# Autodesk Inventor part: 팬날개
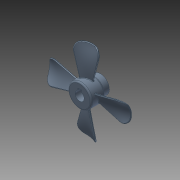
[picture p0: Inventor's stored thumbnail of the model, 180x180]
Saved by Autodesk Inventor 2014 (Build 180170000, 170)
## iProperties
Company: 한국ATC센터
Created: 2016-06
Part Number: 팬날개
Document SubType Name: Modeling
Designer: mdu
Density: 1.06 g/cm^3
Material: ABS 플라스틱
Mass: 29.2304 g
Surface Area: 148.222 cm^2
Volume: 27.5759 cm^3
Appearance: 강청색
Author: mdu
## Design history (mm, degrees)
sketch "스케치1"
  geometry: L1 (-15, 0)-(15, 0); L2 (-15, 0)-(-15, 17); L3 (-15, 17)-(5, 17); L4 (5, 17)-(5, 13); L5 (5, 13)-(15, 13); L6 (15, 13)-(15, 0); 2 further points
  constraints: 12 end point, 3 parallel, 2 perpendicular, 1 coincident, 1 horizontal, 1 midpoint
  dimensions: "d0" = 30 distance of L1.start L1.end; "d8" = 34 diameter of L3 L1; "d10" = 26 diameter of L5 L1; "d32" = 20 distance of L2.end L3.end
revolve "회전1" sketch "스케치1" stored, may be unused: angle "d11" = 90 deg
node "작업 평면2"
sketch "스케치7"
  geometry: L1 (-15, 17)-(5, 17) reference; L2 (-15, -17)-(5, -17) reference; L3 (-5, 17)-(-5, -17); A1 r 35 centre (-36.399, -13.457) between (-2, -7) and (-8, 7); 1 further point
  constraints: 2 end point, 2 midpoint, 2 point on circle, 1 centre point
  dimensions: "d36" = 35 radius of A1; "d37" = 10 distance from line of A1.start L2; "d38" = 10 distance from line of A1.end L1; "d45" = 3 distance from line of A1.end L3; "d46" = 3 distance from line of A1.start L3
sketch "3D 스케치1"
  geometry: L1 through (0, 0) direction (1, 0) reference; L2 through (0, 0) direction (1, 0) reference; 13 other entities
  constraints: 2 collinear
  node "투영 원본 위치 스케치7"
sketch "스케치8"
  geometry: L1 (-15, 17)-(5, 17) reference; L2 (-15, -17)-(5, -17) reference; L3 (-5, 17)-(-5, -17); A1 r 30 centre (-28.74, -3.591) between (-3, -19) and (-9, 19); 1 further point
  constraints: 2 end point, 2 midpoint, 2 point on circle, 1 centre point
  dimensions: "d43" = 30 radius of A1; "d47" = 4 distance from line of A1.end L3; "d48" = 2 distance from line of A1.start L3; "d58" = 2 distance from line of A1.end L1; "d59" = 2 distance from line of A1.start L2
sketch "3D 스케치2"
sketch "3D 스케치3"
feature "경계 패치1" sketch "3D 스케치2", "3D 스케치3" dims "d50" = 0
feature "연장1" dims "d55" = 2
feature "두껍게 하기1" dims "d51" = 2, "d52" = 2
sketch "스케치9"
  geometry: C1 r 59 at (0, 0); 1 further point
  constraints: 1 centre point, 1 coincident
  dimensions: "d60" = 118 diameter of C1
extrude "돌출2" sketch "스케치9" distance "d62" = 200; taper "d63" = 0 deg
fillet "모깎기6" dims "d64" = 10
fillet "모깎기7" dims "d66" = 0.8
fillet "모깎기8" dims "d67" = 0.8
sketch "스케치2"
  geometry: L1 (-2.5, 6)-(-2.5, 8.8); L2 (-2.5, 8.8)-(2.5, 8.8); L3 (2.5, 8.8)-(2.5, 6); A1 r 6.5 centre (0, 0) between (-2.5, 6) and (2.5, 6); 1 further point
  constraints: 6 end point, 2 parallel, 2 point on circle, 1 centre point, 1 coincident, 1 horizontal, 1 vertical
  dimensions: "d12" = 13 diameter of A1; "d13" = 5 distance of L1.end L2.end; "d14" = 15.3 dimension on A1 L2 (computed from d12)
extrude "돌출1" cut sketch "스케치2" stored distance "d15" = 10; taper "d16" = 0 deg
chamfer "모따기1" distance "d17" = 1; stored, may be unused: second distance "d18" = 2, angle "d19" = 45 deg
node "작업 평면1"
sketch "스케치3"
  geometry: L1 (5, -13)-(5, 13) reference; 3 further points
  constraints: 1 horizontal alignment, 1 midpoint
  dimensions: "d20" = 5 distance from line of L1 point (0, 0)
hole "구멍1" sketch "스케치3" at (0, 0) diameter "d21" = 3.242; stored, may be unused: countersink angle "d25" = 90 deg, drill point angle "d27" = 118 deg; dims "d22" = 6, "d23" = 4, "d24" = 2, "d26" = 8
fillet "모깎기9" dims "d77" = 2
fillet "모깎기10" dims "d78" = 2
fillet "모깎기11" dims "d79" = 2
node "솔리드1"
pattern_circular "원형 패턴1" dims "d69" = 360 deg
pattern_circular "원형 패턴2" dims angle "d72" = 360 deg
pattern_circular "원형 패턴3" dims angle "d75" = 360 deg
node "투영 원본 위치 스케치8"
node "곡면1"
node "곡면2"
node "곡면3"
node "곡면4"
feature "경계 패치2"
feature "경계 패치3"
feature "경계 패치4"
